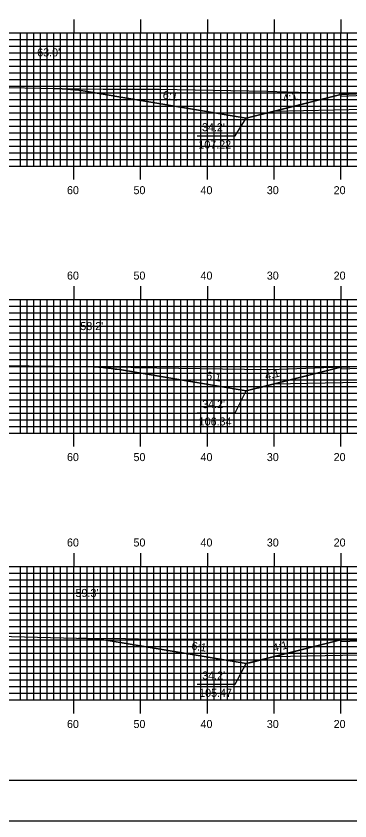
# Model space of a CAD drawing. Extents: x 1779499 to 1779842, y 442591 to 442811.
# Drawn here: x 1779596.2 to 1779646.2, y 442590.5 to 442711.2 of the extents above; entities that cross this region are included whole.
import ezdxf

# ---------------------------------------------------------------- set-up
doc = ezdxf.new("R2010")
doc.units = 0
for name, color, linetype in [('ANNOTATION', 7, 'Continuous'), ('BORDER', 7, 'Continuous'), ('D_Roadway_Centerline', 7, 'Continuous'), ('D_Roadway_Edge_Shoulder', 7, 'Continuous'), ('D_Roadway_SlopeLines', 7, 'Continuous'), ('D_Roadway_SubGrade', 7, 'Continuous'), ('D_Text_Standard', 7, 'Continuous'), ('H_V ANNOTATION', 7, 'Continuous'), ('MAJOR', 7, 'Continuous'), ('MINOR', 7, 'Continuous'), ('PLOT BOUNDARY', 7, 'Continuous'), ('S_Roadway_Centerline', 7, 'Continuous')]:
    doc.layers.add(name, color=color, linetype=linetype)

msp = doc.modelspace()

# ---------------------------------------------------------------- linework, layer by layer
at = {"layer": 'ANNOTATION'}
for points in [[(1779623.29, 442693.19), (1779628.98, 442693.19), (1779630.67, 442695.88)], [(1779623.32, 442651.69), (1779629.01, 442651.69), (1779630.67, 442655.01)], [(1779623.33, 442611.02), (1779629.02, 442611.02), (1779630.67, 442614.13)]]:
    msp.add_lwpolyline(points, dxfattribs=at)
at = {"layer": 'BORDER'}
msp.add_lwpolyline([(1779515.24, 442596.67), (1779835.24, 442596.67), (1779835.24, 442806.67), (1779515.24, 442806.67)], close=True, dxfattribs=at)
at = {"layer": 'D_Roadway_Centerline'}
for points in [[(1779601.84, 442700.31), (1779603.09, 442700.27), (1779604.34, 442700.18), (1779605.59, 442700.04), (1779606.84, 442699.86), (1779630.67, 442695.88), (1779634.67, 442696.88), (1779644.84, 442699.43), (1779652.84, 442699.75), (1779664.84, 442699.99), (1779676.84, 442699.75), (1779684.84, 442699.43), (1779695.02, 442696.88), (1779699.02, 442695.88), (1779715.57, 442698.64), (1779716.82, 442698.83), (1779718.07, 442698.97), (1779719.32, 442699.07), (1779720.57, 442699.12)], [(1779606.66, 442658.63), (1779607.91, 442658.59), (1779609.16, 442658.5), (1779610.41, 442658.36), (1779611.66, 442658.18), (1779630.67, 442655.01), (1779634.67, 442656.01), (1779644.84, 442658.55), (1779652.84, 442658.87), (1779664.84, 442659.11), (1779676.84, 442658.87), (1779684.84, 442658.55), (1779695.02, 442656.01), (1779699.02, 442655.01), (1779713.54, 442657.43), (1779714.79, 442657.61), (1779716.04, 442657.74), (1779717.29, 442657.81), (1779718.54, 442657.83)], [(1779606.84, 442658.63), (1779607.91, 442658.59), (1779609.16, 442658.5), (1779609.5, 442658.46)], [(1779611.02, 442658.27), (1779611.66, 442658.18), (1779622.62, 442656.35)], [(1779632.33, 442655.42), (1779634.67, 442656.01), (1779637.96, 442656.83)], [(1779605.58, 442617.93), (1779605.94, 442617.92), (1779606.83, 442617.89), (1779608.08, 442617.8), (1779608.6, 442617.75), (1779609.33, 442617.67), (1779610.58, 442617.48), (1779610.58, 442617.48), (1779630.67, 442614.13), (1779631.38, 442614.31), (1779634.67, 442615.13), (1779644.84, 442617.68), (1779652.84, 442618)]]:
    msp.add_lwpolyline(points, dxfattribs=at)
at = {"layer": 'D_Roadway_Edge_Shoulder'}
for points in [[(1779652.84, 442699.75), (1779644.84, 442699.43), (1779644.84, 442699.18), (1779652.84, 442699.5)], [(1779652.84, 442658.87), (1779644.84, 442658.55), (1779644.84, 442658.3), (1779652.84, 442658.62)], [(1779652.84, 442658.87), (1779644.84, 442658.55), (1779644.84, 442658.3), (1779652.84, 442658.62)], [(1779652.84, 442618), (1779644.84, 442617.68), (1779644.84, 442617.43), (1779652.84, 442617.75)]]:
    msp.add_lwpolyline(points, close=True, dxfattribs=at)
at = {"layer": 'D_Roadway_SlopeLines'}
for points in [[(1779630.67, 442695.88), (1779606.84, 442699.86), (1779605.59, 442700.04), (1779604.34, 442700.18), (1779603.09, 442700.27), (1779601.84, 442700.31)], [(1779644.84, 442699.43), (1779630.67, 442695.88)], [(1779630.67, 442655.01), (1779611.66, 442658.18), (1779610.41, 442658.36), (1779609.16, 442658.5), (1779607.91, 442658.59), (1779606.66, 442658.63)], [(1779630.67, 442655.01), (1779611.66, 442658.18), (1779610.41, 442658.36), (1779609.16, 442658.5), (1779607.91, 442658.59), (1779606.66, 442658.63)], [(1779644.84, 442658.55), (1779630.67, 442655.01)], [(1779644.84, 442658.55), (1779630.67, 442655.01)], [(1779630.67, 442614.13), (1779610.58, 442617.48), (1779609.33, 442617.67), (1779608.08, 442617.8), (1779606.83, 442617.89), (1779605.58, 442617.93)], [(1779644.84, 442617.68), (1779630.67, 442614.13)]]:
    msp.add_lwpolyline(points, dxfattribs=at)
at = {"layer": 'D_Roadway_SubGrade'}
for points in [[(1779652.84, 442697.25), (1779634.67, 442696.88), (1779644.84, 442699.43), (1779644.84, 442699.18), (1779652.84, 442699.5), (1779664.84, 442699.74), (1779676.84, 442699.5), (1779684.84, 442699.18), (1779684.84, 442699.43), (1779695.02, 442696.88), (1779676.84, 442697.25), (1779664.84, 442697.49)], [(1779652.84, 442656.37), (1779634.67, 442656.01), (1779644.84, 442658.55), (1779644.84, 442658.3), (1779652.84, 442658.62), (1779664.84, 442658.86), (1779676.84, 442658.62), (1779684.84, 442658.3), (1779684.84, 442658.55), (1779695.02, 442656.01), (1779676.84, 442656.37), (1779664.84, 442656.61)], [(1779652.84, 442656.37), (1779634.67, 442656.01), (1779644.84, 442658.55), (1779644.84, 442658.3), (1779652.84, 442658.62), (1779664.84, 442658.86), (1779676.84, 442658.62), (1779684.84, 442658.3), (1779684.84, 442658.55), (1779695.02, 442656.01), (1779676.84, 442656.37), (1779664.84, 442656.61)], [(1779652.84, 442615.5), (1779634.67, 442615.13), (1779644.84, 442617.68), (1779644.84, 442617.43), (1779652.84, 442617.75), (1779664.84, 442617.99), (1779676.84, 442617.75), (1779684.84, 442617.43), (1779684.84, 442617.68), (1779695.02, 442615.13), (1779676.84, 442615.5), (1779664.84, 442615.74)]]:
    msp.add_lwpolyline(points, close=True, dxfattribs=at)
at = {"layer": 'MAJOR'}
for p, q in [((1779604.84, 442710.67), (1779604.84, 442708.67)), ((1779614.84, 442710.67), (1779614.84, 442708.67)), ((1779624.84, 442710.67), (1779624.84, 442708.67)), ((1779634.84, 442710.67), (1779634.84, 442708.67)), ((1779644.84, 442710.67), (1779644.84, 442708.67)), ((1779524.84, 442708.67), (1779804.84, 442708.67)), ((1779524.84, 442708.67), (1779804.84, 442708.67)), ((1779604.84, 442688.67), (1779604.84, 442708.67)), ((1779614.84, 442688.67), (1779614.84, 442708.67)), ((1779624.84, 442688.67), (1779624.84, 442708.67)), ((1779634.84, 442688.67), (1779634.84, 442708.67)), ((1779644.84, 442688.67), (1779644.84, 442708.67)), ((1779524.84, 442703.67), (1779804.84, 442703.67)), ((1779524.84, 442698.67), (1779804.84, 442698.67)), ((1779524.84, 442693.67), (1779804.84, 442693.67)), ((1779524.84, 442688.67), (1779804.84, 442688.67)), ((1779524.84, 442688.67), (1779804.84, 442688.67)), ((1779604.84, 442686.66), (1779604.84, 442688.67)), ((1779614.84, 442686.66), (1779614.84, 442688.67)), ((1779624.84, 442686.66), (1779624.84, 442688.67)), ((1779634.84, 442686.66), (1779634.84, 442688.67)), ((1779644.84, 442686.66), (1779644.84, 442688.67)), ((1779604.84, 442670.67), (1779604.84, 442668.67)), ((1779614.84, 442670.67), (1779614.84, 442668.67)), ((1779624.84, 442670.67), (1779624.84, 442668.67)), ((1779634.84, 442670.67), (1779634.84, 442668.67)), ((1779644.84, 442670.67), (1779644.84, 442668.67)), ((1779524.84, 442668.67), (1779804.84, 442668.67)), ((1779524.84, 442668.67), (1779804.84, 442668.67)), ((1779604.84, 442648.67), (1779604.84, 442668.67)), ((1779614.84, 442648.67), (1779614.84, 442668.67)), ((1779624.84, 442648.67), (1779624.84, 442668.67)), ((1779634.84, 442648.67), (1779634.84, 442668.67)), ((1779644.84, 442648.67), (1779644.84, 442668.67)), ((1779524.84, 442663.67), (1779804.84, 442663.67)), ((1779524.84, 442658.67), (1779804.84, 442658.67)), ((1779524.84, 442653.67), (1779804.84, 442653.67)), ((1779524.84, 442648.67), (1779804.84, 442648.67)), ((1779524.84, 442648.67), (1779804.84, 442648.67)), ((1779604.84, 442646.66), (1779604.84, 442648.67)), ((1779614.84, 442646.66), (1779614.84, 442648.67)), ((1779624.84, 442646.66), (1779624.84, 442648.67)), ((1779634.84, 442646.66), (1779634.84, 442648.67)), ((1779644.84, 442646.66), (1779644.84, 442648.67)), ((1779604.84, 442630.67), (1779604.84, 442628.67)), ((1779614.84, 442630.67), (1779614.84, 442628.67)), ((1779624.84, 442630.67), (1779624.84, 442628.67)), ((1779634.84, 442630.67), (1779634.84, 442628.67)), ((1779644.84, 442630.67), (1779644.84, 442628.67)), ((1779524.84, 442628.67), (1779804.84, 442628.67)), ((1779524.84, 442628.67), (1779804.84, 442628.67)), ((1779604.84, 442608.67), (1779604.84, 442628.67)), ((1779614.84, 442608.67), (1779614.84, 442628.67)), ((1779624.84, 442608.67), (1779624.84, 442628.67)), ((1779634.84, 442608.67), (1779634.84, 442628.67)), ((1779644.84, 442608.67), (1779644.84, 442628.67)), ((1779524.84, 442623.67), (1779804.84, 442623.67)), ((1779524.84, 442618.67), (1779804.84, 442618.67)), ((1779524.84, 442613.67), (1779804.84, 442613.67)), ((1779524.84, 442608.67), (1779804.84, 442608.67)), ((1779524.84, 442608.67), (1779804.84, 442608.67)), ((1779604.84, 442606.66), (1779604.84, 442608.67)), ((1779614.84, 442606.66), (1779614.84, 442608.67)), ((1779624.84, 442606.66), (1779624.84, 442608.67)), ((1779634.84, 442606.66), (1779634.84, 442608.67)), ((1779644.84, 442606.66), (1779644.84, 442608.67))]:
    msp.add_line(p, q, dxfattribs=at)
at = {"layer": 'MINOR'}
for p, q in [((1779596.84, 442688.67), (1779596.84, 442708.67)), ((1779597.84, 442688.67), (1779597.84, 442708.67)), ((1779598.84, 442688.67), (1779598.84, 442708.67)), ((1779599.84, 442688.67), (1779599.84, 442708.67)), ((1779600.84, 442688.67), (1779600.84, 442708.67)), ((1779601.84, 442688.67), (1779601.84, 442708.67)), ((1779602.84, 442688.67), (1779602.84, 442708.67)), ((1779603.84, 442688.67), (1779603.84, 442708.67)), ((1779605.84, 442688.67), (1779605.84, 442708.67)), ((1779606.84, 442688.67), (1779606.84, 442708.67)), ((1779607.84, 442688.67), (1779607.84, 442708.67)), ((1779608.84, 442688.67), (1779608.84, 442708.67)), ((1779609.84, 442688.67), (1779609.84, 442708.67)), ((1779610.84, 442688.67), (1779610.84, 442708.67)), ((1779611.84, 442688.67), (1779611.84, 442708.67)), ((1779612.84, 442688.67), (1779612.84, 442708.67)), ((1779613.84, 442688.67), (1779613.84, 442708.67)), ((1779615.84, 442688.67), (1779615.84, 442708.67)), ((1779616.84, 442688.67), (1779616.84, 442708.67)), ((1779617.84, 442688.67), (1779617.84, 442708.67)), ((1779618.84, 442688.67), (1779618.84, 442708.67)), ((1779619.84, 442688.67), (1779619.84, 442708.67)), ((1779620.84, 442688.67), (1779620.84, 442708.67)), ((1779621.84, 442688.67), (1779621.84, 442708.67)), ((1779622.84, 442688.67), (1779622.84, 442708.67)), ((1779623.84, 442688.67), (1779623.84, 442708.67)), ((1779625.84, 442688.67), (1779625.84, 442708.67)), ((1779626.84, 442688.67), (1779626.84, 442708.67)), ((1779627.84, 442688.67), (1779627.84, 442708.67)), ((1779628.84, 442688.67), (1779628.84, 442708.67)), ((1779629.84, 442688.67), (1779629.84, 442708.67)), ((1779630.84, 442688.67), (1779630.84, 442708.67)), ((1779631.84, 442688.67), (1779631.84, 442708.67)), ((1779632.84, 442688.67), (1779632.84, 442708.67)), ((1779633.84, 442688.67), (1779633.84, 442708.67)), ((1779635.84, 442688.67), (1779635.84, 442708.67)), ((1779636.84, 442688.67), (1779636.84, 442708.67)), ((1779637.84, 442688.67), (1779637.84, 442708.67)), ((1779638.84, 442688.67), (1779638.84, 442708.67)), ((1779639.84, 442688.67), (1779639.84, 442708.67)), ((1779640.84, 442688.67), (1779640.84, 442708.67)), ((1779641.84, 442688.67), (1779641.84, 442708.67)), ((1779642.84, 442688.67), (1779642.84, 442708.67)), ((1779643.84, 442688.67), (1779643.84, 442708.67)), ((1779645.84, 442688.67), (1779645.84, 442708.67)), ((1779524.84, 442707.67), (1779804.84, 442707.67)), ((1779524.84, 442706.67), (1779804.84, 442706.67)), ((1779524.84, 442705.67), (1779804.84, 442705.67)), ((1779524.84, 442704.67), (1779804.84, 442704.67)), ((1779524.84, 442702.67), (1779804.84, 442702.67)), ((1779524.84, 442701.67), (1779804.84, 442701.67)), ((1779524.84, 442700.67), (1779804.84, 442700.67)), ((1779524.84, 442699.67), (1779804.84, 442699.67)), ((1779524.84, 442697.67), (1779804.84, 442697.67)), ((1779524.84, 442696.67), (1779804.84, 442696.67)), ((1779524.84, 442695.67), (1779804.84, 442695.67)), ((1779524.84, 442694.67), (1779804.84, 442694.67)), ((1779524.84, 442692.67), (1779804.84, 442692.67)), ((1779524.84, 442691.67), (1779804.84, 442691.67)), ((1779524.84, 442690.67), (1779804.84, 442690.67)), ((1779524.84, 442689.67), (1779804.84, 442689.67)), ((1779596.84, 442648.67), (1779596.84, 442668.67)), ((1779597.84, 442648.67), (1779597.84, 442668.67)), ((1779598.84, 442648.67), (1779598.84, 442668.67)), ((1779599.84, 442648.67), (1779599.84, 442668.67)), ((1779600.84, 442648.67), (1779600.84, 442668.67)), ((1779601.84, 442648.67), (1779601.84, 442668.67)), ((1779602.84, 442648.67), (1779602.84, 442668.67)), ((1779603.84, 442648.67), (1779603.84, 442668.67)), ((1779605.84, 442648.67), (1779605.84, 442668.67)), ((1779606.84, 442648.67), (1779606.84, 442668.67)), ((1779607.84, 442648.67), (1779607.84, 442668.67)), ((1779608.84, 442648.67), (1779608.84, 442668.67)), ((1779609.84, 442648.67), (1779609.84, 442668.67)), ((1779610.84, 442648.67), (1779610.84, 442668.67)), ((1779611.84, 442648.67), (1779611.84, 442668.67)), ((1779612.84, 442648.67), (1779612.84, 442668.67)), ((1779613.84, 442648.67), (1779613.84, 442668.67)), ((1779615.84, 442648.67), (1779615.84, 442668.67)), ((1779616.84, 442648.67), (1779616.84, 442668.67)), ((1779617.84, 442648.67), (1779617.84, 442668.67)), ((1779618.84, 442648.67), (1779618.84, 442668.67)), ((1779619.84, 442648.67), (1779619.84, 442668.67)), ((1779620.84, 442648.67), (1779620.84, 442668.67)), ((1779621.84, 442648.67), (1779621.84, 442668.67)), ((1779622.84, 442648.67), (1779622.84, 442668.67)), ((1779623.84, 442648.67), (1779623.84, 442668.67)), ((1779625.84, 442648.67), (1779625.84, 442668.67)), ((1779626.84, 442648.67), (1779626.84, 442668.67)), ((1779627.84, 442648.67), (1779627.84, 442668.67)), ((1779628.84, 442648.67), (1779628.84, 442668.67)), ((1779629.84, 442648.67), (1779629.84, 442668.67)), ((1779630.84, 442648.67), (1779630.84, 442668.67)), ((1779631.84, 442648.67), (1779631.84, 442668.67)), ((1779632.84, 442648.67), (1779632.84, 442668.67)), ((1779633.84, 442648.67), (1779633.84, 442668.67)), ((1779635.84, 442648.67), (1779635.84, 442668.67)), ((1779636.84, 442648.67), (1779636.84, 442668.67)), ((1779637.84, 442648.67), (1779637.84, 442668.67)), ((1779638.84, 442648.67), (1779638.84, 442668.67)), ((1779639.84, 442648.67), (1779639.84, 442668.67)), ((1779640.84, 442648.67), (1779640.84, 442668.67)), ((1779641.84, 442648.67), (1779641.84, 442668.67)), ((1779642.84, 442648.67), (1779642.84, 442668.67)), ((1779643.84, 442648.67), (1779643.84, 442668.67)), ((1779645.84, 442648.67), (1779645.84, 442668.67)), ((1779524.84, 442667.67), (1779804.84, 442667.67)), ((1779524.84, 442666.67), (1779804.84, 442666.67)), ((1779524.84, 442665.67), (1779804.84, 442665.67)), ((1779524.84, 442664.67), (1779804.84, 442664.67)), ((1779524.84, 442662.67), (1779804.84, 442662.67)), ((1779524.84, 442661.67), (1779804.84, 442661.67)), ((1779524.84, 442660.67), (1779804.84, 442660.67)), ((1779524.84, 442659.67), (1779804.84, 442659.67)), ((1779524.84, 442657.67), (1779804.84, 442657.67)), ((1779524.84, 442656.67), (1779804.84, 442656.67)), ((1779524.84, 442655.67), (1779804.84, 442655.67)), ((1779524.84, 442654.67), (1779804.84, 442654.67)), ((1779524.84, 442652.67), (1779804.84, 442652.67)), ((1779524.84, 442651.67), (1779804.84, 442651.67)), ((1779524.84, 442650.67), (1779804.84, 442650.67)), ((1779524.84, 442649.67), (1779804.84, 442649.67)), ((1779596.84, 442608.67), (1779596.84, 442628.67)), ((1779597.84, 442608.67), (1779597.84, 442628.67)), ((1779598.84, 442608.67), (1779598.84, 442628.67)), ((1779599.84, 442608.67), (1779599.84, 442628.67)), ((1779600.84, 442608.67), (1779600.84, 442628.67)), ((1779601.84, 442608.67), (1779601.84, 442628.67)), ((1779602.84, 442608.67), (1779602.84, 442628.67)), ((1779603.84, 442608.67), (1779603.84, 442628.67)), ((1779605.84, 442608.67), (1779605.84, 442628.67)), ((1779606.84, 442608.67), (1779606.84, 442628.67)), ((1779607.84, 442608.67), (1779607.84, 442628.67)), ((1779608.84, 442608.67), (1779608.84, 442628.67)), ((1779609.84, 442608.67), (1779609.84, 442628.67)), ((1779610.84, 442608.67), (1779610.84, 442628.67)), ((1779611.84, 442608.67), (1779611.84, 442628.67)), ((1779612.84, 442608.67), (1779612.84, 442628.67)), ((1779613.84, 442608.67), (1779613.84, 442628.67)), ((1779615.84, 442608.67), (1779615.84, 442628.67)), ((1779616.84, 442608.67), (1779616.84, 442628.67)), ((1779617.84, 442608.67), (1779617.84, 442628.67)), ((1779618.84, 442608.67), (1779618.84, 442628.67)), ((1779619.84, 442608.67), (1779619.84, 442628.67)), ((1779620.84, 442608.67), (1779620.84, 442628.67)), ((1779621.84, 442608.67), (1779621.84, 442628.67)), ((1779622.84, 442608.67), (1779622.84, 442628.67)), ((1779623.84, 442608.67), (1779623.84, 442628.67)), ((1779625.84, 442608.67), (1779625.84, 442628.67)), ((1779626.84, 442608.67), (1779626.84, 442628.67)), ((1779627.84, 442608.67), (1779627.84, 442628.67)), ((1779628.84, 442608.67), (1779628.84, 442628.67)), ((1779629.84, 442608.67), (1779629.84, 442628.67)), ((1779630.84, 442608.67), (1779630.84, 442628.67)), ((1779631.84, 442608.67), (1779631.84, 442628.67)), ((1779632.84, 442608.67), (1779632.84, 442628.67)), ((1779633.84, 442608.67), (1779633.84, 442628.67)), ((1779635.84, 442608.67), (1779635.84, 442628.67)), ((1779636.84, 442608.67), (1779636.84, 442628.67)), ((1779637.84, 442608.67), (1779637.84, 442628.67)), ((1779638.84, 442608.67), (1779638.84, 442628.67)), ((1779639.84, 442608.67), (1779639.84, 442628.67)), ((1779640.84, 442608.67), (1779640.84, 442628.67)), ((1779641.84, 442608.67), (1779641.84, 442628.67)), ((1779642.84, 442608.67), (1779642.84, 442628.67)), ((1779643.84, 442608.67), (1779643.84, 442628.67)), ((1779645.84, 442608.67), (1779645.84, 442628.67)), ((1779524.84, 442627.67), (1779804.84, 442627.67)), ((1779524.84, 442626.67), (1779804.84, 442626.67)), ((1779524.84, 442625.67), (1779804.84, 442625.67)), ((1779524.84, 442624.67), (1779804.84, 442624.67)), ((1779524.84, 442622.67), (1779804.84, 442622.67)), ((1779524.84, 442621.67), (1779804.84, 442621.67)), ((1779524.84, 442620.67), (1779804.84, 442620.67)), ((1779524.84, 442619.67), (1779804.84, 442619.67)), ((1779524.84, 442617.67), (1779804.84, 442617.67)), ((1779524.84, 442616.67), (1779804.84, 442616.67)), ((1779524.84, 442615.67), (1779804.84, 442615.67)), ((1779524.84, 442614.67), (1779804.84, 442614.67)), ((1779524.84, 442612.67), (1779804.84, 442612.67)), ((1779524.84, 442611.67), (1779804.84, 442611.67)), ((1779524.84, 442610.67), (1779804.84, 442610.67)), ((1779524.84, 442609.67), (1779804.84, 442609.67))]:
    msp.add_line(p, q, dxfattribs=at)
at = {"layer": 'PLOT BOUNDARY'}
msp.add_lwpolyline([(1779499.06, 442590.55), (1779839.06, 442590.55), (1779839.06, 442810.55), (1779499.06, 442810.55)], close=True, dxfattribs=at)
at = {"layer": 'S_Roadway_Centerline'}
for points in [[(1779524.84, 442700.98), (1779542.07, 442701.21), (1779543.7, 442701.23), (1779545.73, 442701.17), (1779564.52, 442700.55), (1779578.32, 442700.89), (1779587.23, 442700.78), (1779589.84, 442700.56), (1779592.77, 442700.52), (1779602.15, 442700.3), (1779609.24, 442700.21), (1779617.64, 442700.19), (1779633.75, 442699.89), (1779636.78, 442699.8), (1779640.23, 442699.7), (1779648.88, 442699.52), (1779656.08, 442699.28), (1779664.38, 442699.29), (1779678.74, 442699.37), (1779688.72, 442699.14), (1779695.35, 442698.99), (1779700.89, 442698.9), (1779712.94, 442698.94), (1779723.89, 442699.2)], [(1779524.84, 442659.88), (1779539.98, 442659.46), (1779542.33, 442659.47), (1779544.97, 442659.37), (1779563.61, 442659.18), (1779567.85, 442659.18), (1779578, 442659.48), (1779588.47, 442658.91), (1779590.47, 442658.87), (1779613.36, 442658.53), (1779613.97, 442658.52), (1779633.71, 442658.2), (1779633.94, 442658.2), (1779634.26, 442658.21), (1779647.62, 442658.69), (1779656.69, 442658.51), (1779657.63, 442658.51), (1779669.74, 442658.69), (1779679.85, 442658.14), (1779684.37, 442658.08), (1779694.36, 442658.53), (1779704.27, 442658.02), (1779707.72, 442657.91), (1779724.69, 442657.78)], [(1779524.84, 442618.79), (1779530.01, 442618.67), (1779535.32, 442618.69), (1779548.07, 442619.12), (1779561.14, 442619.11), (1779569.92, 442618.82), (1779583.27, 442618.54), (1779593.48, 442618.25), (1779607.16, 442617.89), (1779610.65, 442617.93), (1779614.51, 442617.84), (1779630.75, 442617.76), (1779637.65, 442617.81), (1779653.86, 442617.87), (1779661.06, 442617.69), (1779672.26, 442617.35), (1779677.72, 442617.3), (1779692.08, 442617.4), (1779701.61, 442617.01), (1779706.69, 442616.88), (1779709.87, 442617.02), (1779717.48, 442617.16), (1779727.58, 442616.98)]]:
    msp.add_lwpolyline(points, dxfattribs=at)

# ---------------------------------------------------------------- texts
at = {"layer": 'ANNOTATION'}
for s, rotation, p in [('6:1', 350.5377, (1779618.09, 442698.81)), ('4:1', 14.0362, (1779636.29, 442698.15)), ('6:1', 350.5377, (1779624.6, 442656.74)), ('4:1', 14.0362, (1779633.6, 442656.62)), ('4:1', 14.0347, (1779634.78, 442615.86)), ('6:1', 350.5369, (1779622.39, 442616.26))]:
    msp.add_text(s, height=1.2, rotation=rotation, dxfattribs=at).set_placement(p)
for s, p in [("34.2'", (1779624.03, 442693.91)), ('107.22', (1779623.49, 442691.31)), ("34.2'", (1779624.06, 442652.41)), ('106.34', (1779623.54, 442649.81)), ("34.2'", (1779624.06, 442611.74)), ('105.47', (1779623.61, 442609.14))]:
    msp.add_text(s, height=1.2, dxfattribs=at).set_placement(p)
at = {"layer": 'D_Text_Standard'}
for s, p in [("63.0'", (1779599.35, 442705.12)), ("58.2'", (1779605.81, 442664.1)), ("59.3'", (1779605.09, 442624.11))]:
    msp.add_text(s, height=1.2, dxfattribs=at).set_placement(p)
at = {"layer": 'H_V ANNOTATION'}
for s, p in [('60', (1779603.81, 442684.47)), ('50', (1779613.77, 442684.47)), ('40', (1779623.81, 442684.47)), ('30', (1779633.74, 442684.47)), ('20', (1779643.75, 442684.47)), ('60', (1779603.81, 442671.67)), ('50', (1779613.77, 442671.67)), ('40', (1779623.81, 442671.67)), ('30', (1779633.74, 442671.67)), ('20', (1779643.75, 442671.67)), ('60', (1779603.81, 442644.47)), ('50', (1779613.77, 442644.47)), ('40', (1779623.81, 442644.47)), ('30', (1779633.74, 442644.47)), ('20', (1779643.75, 442644.47)), ('60', (1779603.81, 442631.67)), ('50', (1779613.77, 442631.67)), ('40', (1779623.81, 442631.67)), ('30', (1779633.74, 442631.67)), ('20', (1779643.75, 442631.67)), ('60', (1779603.81, 442604.47)), ('50', (1779613.77, 442604.47)), ('40', (1779623.81, 442604.47)), ('30', (1779633.74, 442604.47)), ('20', (1779643.75, 442604.47))]:
    msp.add_text(s, height=1.2, dxfattribs=at).set_placement(p)

doc.saveas('drawing.dxf')
